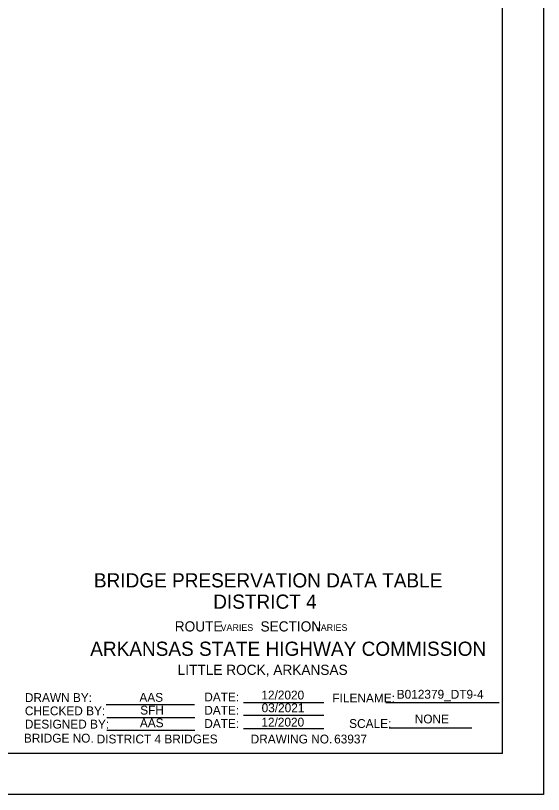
# Model space of a CAD drawing. Extents: x 16 to 1228740, y 11 to 152440.
# Drawn here: x 17.87 to 18.49, y 10.709 to 11.626 of the extents above; entities that cross this region are included whole.
import ezdxf

# ---------------------------------------------------------------- set-up
doc = ezdxf.new("R2010")
doc.units = 0
for name, color, linetype in [('B_Copy In', 7, 'Continuous'), ('B_Text', 7, 'Continuous'), ('B_Title Text', 7, 'Continuous'), ('R_Border', 7, 'Continuous')]:
    doc.layers.add(name, color=color, linetype=linetype)

msp = doc.modelspace()

# ---------------------------------------------------------------- linework, layer by layer
at = {"layer": 'B_Text'}
for p, q in [((17.97661, 10.81515), (18.08021, 10.81515)), ((18.13771, 10.81765), (18.23221, 10.81765)), ((18.30529, 10.81765), (18.43835, 10.81765)), ((18.13771, 10.80265), (18.23221, 10.80265)), ((18.13771, 10.80265), (18.23221, 10.80265)), ((17.97721, 10.80015), (18.08081, 10.80015)), ((17.97721, 10.78515), (18.08081, 10.78515)), ((18.13771, 10.78703), (18.23221, 10.78703)), ((18.30917, 10.78765), (18.40631, 10.78765))]:
    msp.add_line(p, q, dxfattribs=at)
at = {"layer": 'R_Border'}
for q in [(18.44221, 12.49475), (15.78327, 10.75755)]:
    msp.add_line((18.44221, 10.75755), q, dxfattribs=at)
msp.add_lwpolyline([(15.65694, 12.54282), (18.49027, 12.54282), (18.49027, 10.70949), (15.65694, 10.70949)], close=True, dxfattribs=at)

# ---------------------------------------------------------------- texts
at = {"layer": 'B_Copy In'}
for s, height, p in [('BRIDGE PRESERVATION DATA TABLE ', 0.0167, (17.96204, 10.95296)), ('DISTRICT 4', 0.0167, (18.10227, 10.92791)), ('12/2020', 0.0104, (18.15886, 10.82119)), ('B012379_DT9-4', 0.0104, (18.31792, 10.8221)), ('AAS', 0.0104, (18.0155, 10.81846)), ('SFH', 0.0104, (18.01647, 10.80346)), ('03/2021', 0.0104, (18.15915, 10.80619)), ('NONE', 0.0104, (18.3391, 10.79302)), ('AAS', 0.0104, (18.0161, 10.78846)), ('12/2020', 0.0104, (18.15886, 10.78934)), ('DISTRICT 4 BRIDGES', 0.0104, (17.96528, 10.76948)), ('63937', 0.0104, (18.24434, 10.76945))]:
    msp.add_text(s, height=height, dxfattribs=at).set_placement(p)
at = {"layer": 'B_Text'}
for s, height, p in [('DATE:', 0.010417, (18.09171, 10.8189)), ('DRAWN BY:', 0.010417, (17.88091, 10.8182)), ('FILENAME:', 0.010417, (18.24229, 10.81765)), ('CHECKED BY:', 0.0104166, (17.88091, 10.80257)), ('DATE:', 0.010417, (18.09171, 10.80328)), ('DESIGNED BY:', 0.0104166, (17.88091, 10.78695)), ('DATE:', 0.010417, (18.09171, 10.78765)), ('SCALE:', 0.010417, (18.26201, 10.78765)), ('BRIDGE NO.', 0.010417, (17.87978, 10.77048)), ('DRAWING NO.', 0.0104166, (18.14623, 10.76942))]:
    msp.add_text(s, height=height, dxfattribs=at).set_placement(p)
at = {"layer": 'B_Title Text'}
for s, height, p in [('ROUTE          SECTION ', 0.012, (18.05705, 10.90115)), ('ROUTE          SECTION ', 0.012, (18.05705, 10.90115)), ('                VARIES                         VARIES', 0.0078, (18.06459, 10.9019)), ('ARKANSAS STATE HIGHWAY COMMISSION', 0.0167, (17.95772, 10.8725)), ('LITTLE ROCK, ARKANSAS', 0.012, (18.0605, 10.85007))]:
    msp.add_text(s, height=height, dxfattribs=at).set_placement(p)

doc.saveas('drawing.dxf')
